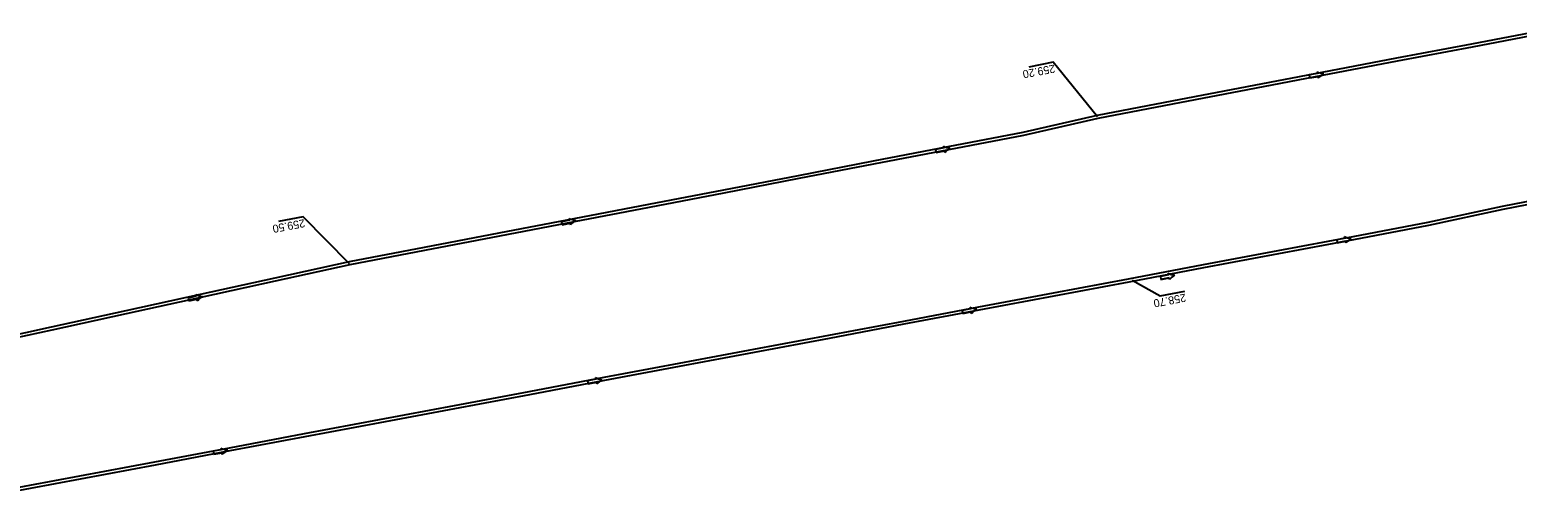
# Model space of a CAD drawing. Extents: x -1 to 65640748, y -22 to 5530284.
# Drawn here: x 6564037.5 to 6564232.6, y 5529914.6 to 5529975.4 of the extents above; entities that cross this region are included whole.
import ezdxf

# ---------------------------------------------------------------- set-up
doc = ezdxf.new("R2010")
doc.units = 0
for name, color, linetype in [('TOR_PS_OPIS_O-opisy rurociagow', 7, 'Continuous'), ('TOR_PS_OPIS_T-INFO', 7, 'Continuous'), ('TOR_PS_T-rowy otwarte umocnione', 7, 'Continuous')]:
    doc.layers.add(name, color=color, linetype=linetype)

msp = doc.modelspace()

# ---------------------------------------------------------------- linework, layer by layer
at = {"layer": 'TOR_PS_OPIS_O-opisy rurociagow'}
for p, q in [((6564206.41, 5529969.71), (6564205.34, 5529969.51)), ((6564206.41, 5529969.71), (6564205.34, 5529969.51)), ((6564205.34, 5529969.51), (6564205.41, 5529969.12)), ((6564205.34, 5529969.51), (6564205.41, 5529969.12)), ((6564205.41, 5529969.12), (6564206.48, 5529969.32)), ((6564206.48, 5529969.32), (6564205.41, 5529969.12)), ((6564157.38, 5529959.94), (6564156.31, 5529959.73)), ((6564157.38, 5529959.94), (6564156.31, 5529959.73)), ((6564156.31, 5529959.73), (6564156.38, 5529959.34)), ((6564156.31, 5529959.73), (6564156.38, 5529959.34)), ((6564156.38, 5529959.34), (6564157.46, 5529959.54)), ((6564157.46, 5529959.54), (6564156.38, 5529959.34)), ((6564108.29, 5529950.45), (6564107.21, 5529950.25)), ((6564108.29, 5529950.45), (6564107.21, 5529950.25)), ((6564107.21, 5529950.25), (6564107.29, 5529949.85)), ((6564107.21, 5529950.25), (6564107.29, 5529949.85)), ((6564107.29, 5529949.85), (6564108.36, 5529950.06)), ((6564108.36, 5529950.06), (6564107.29, 5529949.85)), ((6564210, 5529948.07), (6564208.93, 5529947.87)), ((6564210, 5529948.07), (6564208.93, 5529947.87)), ((6564208.93, 5529947.87), (6564209, 5529947.47)), ((6564208.93, 5529947.87), (6564209, 5529947.47)), ((6564209, 5529947.47), (6564210.08, 5529947.68)), ((6564210.08, 5529947.68), (6564209, 5529947.47)), ((6564186.87, 5529943.26), (6564185.8, 5529943.04)), ((6564186.87, 5529943.26), (6564185.8, 5529943.04)), ((6564185.8, 5529943.04), (6564185.88, 5529942.65)), ((6564185.8, 5529943.04), (6564185.88, 5529942.65)), ((6564185.88, 5529942.65), (6564186.95, 5529942.86)), ((6564186.95, 5529942.86), (6564185.88, 5529942.65)), ((6564059.3, 5529940.46), (6564058.23, 5529940.23)), ((6564059.3, 5529940.46), (6564058.23, 5529940.23)), ((6564058.23, 5529940.23), (6564058.32, 5529939.84)), ((6564058.23, 5529940.23), (6564058.32, 5529939.84)), ((6564058.32, 5529939.84), (6564059.39, 5529940.07)), ((6564059.39, 5529940.07), (6564058.32, 5529939.84)), ((6564160.87, 5529938.81), (6564159.79, 5529938.61)), ((6564160.87, 5529938.81), (6564159.79, 5529938.61)), ((6564159.79, 5529938.61), (6564159.87, 5529938.22)), ((6564159.79, 5529938.61), (6564159.87, 5529938.22)), ((6564159.87, 5529938.22), (6564160.94, 5529938.42)), ((6564160.94, 5529938.42), (6564159.87, 5529938.22)), ((6564111.73, 5529929.56), (6564110.65, 5529929.36)), ((6564111.73, 5529929.56), (6564110.65, 5529929.36)), ((6564110.65, 5529929.36), (6564110.73, 5529928.97)), ((6564110.65, 5529929.36), (6564110.73, 5529928.97)), ((6564110.73, 5529928.97), (6564111.8, 5529929.17)), ((6564111.8, 5529929.17), (6564110.73, 5529928.97)), ((6564062.59, 5529920.31), (6564061.52, 5529920.11)), ((6564062.59, 5529920.31), (6564061.52, 5529920.11)), ((6564061.52, 5529920.11), (6564061.59, 5529919.72)), ((6564061.52, 5529920.11), (6564061.59, 5529919.72)), ((6564061.59, 5529919.72), (6564062.67, 5529919.92)), ((6564062.67, 5529919.92), (6564061.59, 5529919.72))]:
    msp.add_line(p, q, dxfattribs=at)
for points in [[(6564206.36, 5529969.93), (6564206.36, 5529969.93)], [(6564206.52, 5529969.1), (6564206.52, 5529969.1)], [(6564157.33, 5529960.16), (6564157.33, 5529960.16)], [(6564157.49, 5529959.32), (6564157.49, 5529959.32)], [(6564108.23, 5529950.67), (6564108.23, 5529950.67)], [(6564108.4, 5529949.84), (6564108.4, 5529949.84)], [(6564209.95, 5529948.29), (6564209.95, 5529948.29)], [(6564210.11, 5529947.45), (6564210.11, 5529947.45)], [(6564186.82, 5529943.47), (6564186.82, 5529943.47)], [(6564186.98, 5529942.64), (6564186.98, 5529942.64)], [(6564059.24, 5529940.68), (6564059.24, 5529940.68)], [(6564059.42, 5529939.85), (6564059.42, 5529939.85)], [(6564160.81, 5529939.03), (6564160.81, 5529939.03)], [(6564160.97, 5529938.2), (6564160.97, 5529938.2)], [(6564111.68, 5529929.78), (6564111.68, 5529929.78)], [(6564111.83, 5529928.95), (6564111.83, 5529928.95)], [(6564062.54, 5529920.53), (6564062.54, 5529920.53)], [(6564062.7, 5529919.69), (6564062.7, 5529919.69)]]:
    msp.add_lwpolyline(points, dxfattribs=at)
for centre, radius, start, end in [((6564208.27, 5529974.46), 4.92, 247.0978, 257.4796), ((6564206.81, 5529969.93), 0.458, 179.2123, 207.6736), ((6564208.27, 5529974.46), 4.92, 247.0978, 257.4796), ((6564206.81, 5529969.93), 0.458, 179.2123, 207.6736), ((6564206.94, 5529969.27), 0.458, 173.9417, 202.4029), ((6564206.94, 5529969.27), 0.458, 173.9417, 202.4029), ((6564209.96, 5529965.59), 4.92, 124.1357, 134.5175), ((6564209.96, 5529965.59), 4.92, 124.1357, 134.5175), ((6564159.23, 5529964.69), 4.92, 247.2203, 257.6021), ((6564157.79, 5529960.15), 0.458, 179.3348, 207.7961), ((6564159.23, 5529964.69), 4.92, 247.2203, 257.6021), ((6564157.79, 5529960.15), 0.458, 179.3348, 207.7961), ((6564157.91, 5529959.5), 0.458, 174.0642, 202.5254), ((6564157.91, 5529959.5), 0.458, 174.0642, 202.5254), ((6564160.94, 5529955.82), 4.92, 124.2581, 134.64), ((6564160.94, 5529955.82), 4.92, 124.2581, 134.64), ((6564110.14, 5529955.21), 4.92, 247.2259, 257.6077), ((6564108.69, 5529950.67), 0.458, 179.3404, 207.8017), ((6564110.14, 5529955.21), 4.92, 247.2259, 257.6077), ((6564108.69, 5529950.67), 0.458, 179.3404, 207.8017), ((6564108.82, 5529950.01), 0.458, 174.0698, 202.531), ((6564108.82, 5529950.01), 0.458, 174.0698, 202.531), ((6564111.85, 5529946.34), 4.92, 124.2638, 134.6456), ((6564111.85, 5529946.34), 4.92, 124.2638, 134.6456), ((6564211.86, 5529952.82), 4.92, 247.0921, 257.474), ((6564210.41, 5529948.28), 0.458, 179.2067, 207.6679), ((6564211.86, 5529952.82), 4.92, 247.0921, 257.474), ((6564210.41, 5529948.28), 0.458, 179.2067, 207.6679), ((6564210.53, 5529947.63), 0.458, 173.936, 202.3973), ((6564210.53, 5529947.63), 0.458, 173.936, 202.3973), ((6564213.56, 5529943.95), 4.92, 124.13, 134.5119), ((6564213.56, 5529943.95), 4.92, 124.13, 134.5119), ((6564188.7, 5529948.02), 4.92, 247.4516, 257.8335), ((6564187.27, 5529943.47), 0.458, 179.5662, 208.0274), ((6564188.7, 5529948.02), 4.92, 247.4516, 257.8335), ((6564187.27, 5529943.47), 0.458, 179.5662, 208.0274), ((6564187.4, 5529942.82), 0.458, 174.2956, 202.7568), ((6564187.4, 5529942.82), 0.458, 174.2956, 202.7568), ((6564190.45, 5529939.16), 4.92, 124.4895, 134.8714), ((6564190.45, 5529939.16), 4.92, 124.4895, 134.8714), ((6564061.03, 5529945.26), 4.92, 248.6817, 259.0635), ((6564059.7, 5529940.68), 0.458, 180.7962, 209.2575), ((6564061.03, 5529945.26), 4.92, 248.6817, 259.0635), ((6564059.7, 5529940.68), 0.458, 180.7962, 209.2575), ((6564059.84, 5529940.03), 0.458, 175.5256, 203.9868), ((6564059.84, 5529940.03), 0.458, 175.5256, 203.9868), ((6564062.97, 5529936.44), 4.92, 125.7196, 136.1014), ((6564062.97, 5529936.44), 4.92, 125.7196, 136.1014), ((6564162.74, 5529943.56), 4.92, 246.9517, 257.3335), ((6564161.27, 5529939.03), 0.458, 179.0663, 207.5275), ((6564162.74, 5529943.56), 4.92, 246.9517, 257.3335), ((6564161.27, 5529939.03), 0.458, 179.0663, 207.5275), ((6564164.41, 5529934.68), 4.92, 123.9896, 134.3714), ((6564164.41, 5529934.68), 4.92, 123.9896, 134.3714), ((6564161.39, 5529938.37), 0.458, 173.7956, 202.2568), ((6564161.39, 5529938.37), 0.458, 173.7956, 202.2568), ((6564113.6, 5529934.31), 4.92, 246.9573, 257.3391), ((6564112.13, 5529929.77), 0.458, 179.0719, 207.5331), ((6564113.6, 5529934.31), 4.92, 246.9573, 257.3391), ((6564112.13, 5529929.77), 0.458, 179.0719, 207.5331), ((6564112.26, 5529929.12), 0.458, 173.8012, 202.2625), ((6564112.26, 5529929.12), 0.458, 173.8012, 202.2625), ((6564115.27, 5529925.43), 4.92, 123.9952, 134.377), ((6564115.27, 5529925.43), 4.92, 123.9952, 134.377), ((6564064.47, 5529925.06), 4.92, 246.9573, 257.3391), ((6564063, 5529920.52), 0.458, 179.0719, 207.5331), ((6564064.47, 5529925.06), 4.92, 246.9573, 257.3391), ((6564063, 5529920.52), 0.458, 179.0719, 207.5331), ((6564063.12, 5529919.87), 0.458, 173.8012, 202.2625), ((6564063.12, 5529919.87), 0.458, 173.8012, 202.2625), ((6564066.14, 5529916.18), 4.92, 123.9952, 134.377), ((6564066.14, 5529916.18), 4.92, 123.9952, 134.377)]:
    msp.add_arc(centre, radius, start, end, dxfattribs=at)
at = {"layer": 'TOR_PS_OPIS_T-INFO'}
for points in [[(6564177.54, 5529964.02), (6564171.75, 5529971.17), (6564168.52, 5529970.55)], [(6564079.41, 5529944.73), (6564073.32, 5529950.89), (6564070.09, 5529950.27)], [(6564182.1, 5529942.59), (6564185.77, 5529940.5), (6564189.01, 5529941.11)]]:
    msp.add_lwpolyline(points, dxfattribs=at)
at = {"layer": 'TOR_PS_T-rowy otwarte umocnione'}
for points in [[(6564236.44, 5529975.45), (6564226.61, 5529973.57), (6564216.79, 5529971.7), (6564206.97, 5529969.82), (6564197.15, 5529967.95), (6564187.32, 5529966.07), (6564177.5, 5529964.19), (6564167.75, 5529961.95), (6564157.93, 5529960.06), (6564148.11, 5529958.18), (6564138.29, 5529956.29), (6564128.47, 5529954.4), (6564118.65, 5529952.52), (6564108.83, 5529950.63), (6564099.01, 5529948.74), (6564089.19, 5529946.85), (6564079.37, 5529944.97), (6564069.59, 5529942.83), (6564059.82, 5529940.69), (6564050.05, 5529938.56), (6564040.27, 5529936.42), (6564030.5, 5529934.28)], [(6564236.51, 5529975.05), (6564226.69, 5529973.18), (6564216.87, 5529971.3), (6564207.04, 5529969.43), (6564197.22, 5529967.55), (6564187.4, 5529965.68), (6564177.58, 5529963.8), (6564167.82, 5529961.56), (6564158, 5529959.67), (6564148.18, 5529957.78), (6564138.36, 5529955.9), (6564128.54, 5529954.01), (6564118.72, 5529952.12), (6564108.9, 5529950.24), (6564099.08, 5529948.35), (6564089.26, 5529946.46), (6564079.44, 5529944.57), (6564069.67, 5529942.44), (6564059.89, 5529940.3), (6564050.12, 5529938.16), (6564040.35, 5529936.03), (6564030.58, 5529933.89)], [(6564279.74, 5529961.78), (6564230.66, 5529952.24), (6564220.88, 5529950.13), (6564211.05, 5529948.27), (6564201.23, 5529946.42), (6564191.4, 5529944.57), (6564181.57, 5529942.72), (6564171.75, 5529940.87), (6564161.92, 5529939.02), (6564152.09, 5529937.17), (6564142.26, 5529935.32), (6564132.43, 5529933.48), (6564122.61, 5529931.63), (6564112.78, 5529929.78), (6564102.95, 5529927.93), (6564093.12, 5529926.08), (6564083.3, 5529924.23), (6564073.47, 5529922.39), (6564063.64, 5529920.54), (6564053.81, 5529918.69), (6564043.98, 5529916.84), (6564034.16, 5529914.99)], [(6564279.82, 5529961.38), (6564230.73, 5529951.85), (6564220.96, 5529949.73), (6564211.13, 5529947.88), (6564201.3, 5529946.03), (6564191.47, 5529944.18), (6564181.65, 5529942.32), (6564171.82, 5529940.47), (6564161.99, 5529938.63), (6564152.16, 5529936.78), (6564142.34, 5529934.93), (6564132.51, 5529933.08), (6564122.68, 5529931.23), (6564112.85, 5529929.39), (6564103.03, 5529927.54), (6564093.2, 5529925.69), (6564083.37, 5529923.84), (6564073.54, 5529921.99), (6564063.71, 5529920.15), (6564053.89, 5529918.3), (6564044.06, 5529916.45), (6564034.23, 5529914.6)]]:
    msp.add_lwpolyline(points, dxfattribs=at)

# ---------------------------------------------------------------- texts
at = {"layer": 'TOR_PS_OPIS_T-INFO'}
for s, rotation, p in [('259.20', 190.7159, (6564171.88, 5529970.88)), ('259.50', 190.7159, (6564073.46, 5529950.59)), ('258.70', 190.7506, (6564189.05, 5529940.81))]:
    msp.add_text(s, height=1.05, rotation=rotation, dxfattribs=at).set_placement(p)

doc.saveas('drawing.dxf')
